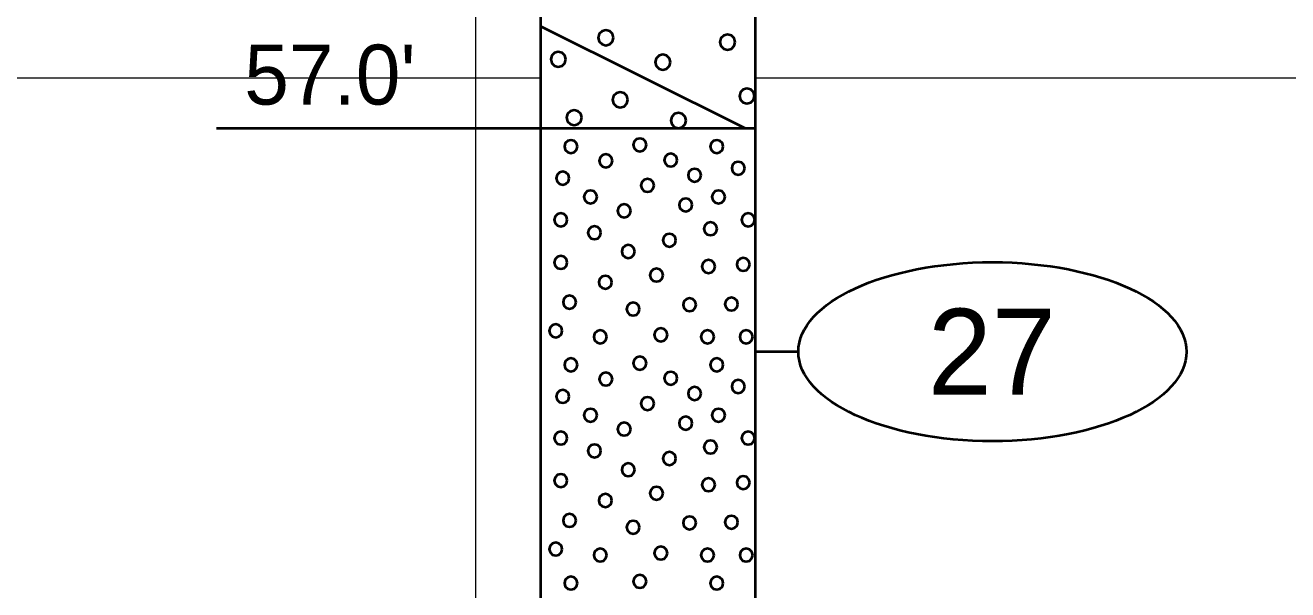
# Model space of a CAD drawing. Extents: x -76 to 974, y -1080 to -735.
# Drawn here: x 658.81 to 673.49, y -988.05 to -981.48 of the extents above; entities that cross this region are included whole.
import ezdxf
from ezdxf.enums import TextEntityAlignment as Align

# ---------------------------------------------------------------- set-up
doc = ezdxf.new("R2010")
doc.units = 0
doc.header["$LTSCALE"] = 0.36
doc.layers.add('27', color=7, linetype='Continuous', lineweight=40)
doc.layers.add('7', color=7, linetype='Continuous', lineweight=13)

msp = doc.modelspace()

# ---------------------------------------------------------------- linework, layer by layer
at = {"layer": '27'}
for p, q in [((664.7963, -977.6789), (664.7963, -982.6789)), ((667.2963, -982.6789), (667.2963, -977.6789)), ((664.7963, -981.4889), (667.1763, -982.6789)), ((661.0289, -982.6789), (664.7963, -982.6789)), ((664.7963, -982.6789), (667.2963, -982.6789)), ((664.7963, -982.6789), (664.7963, -995.7789)), ((667.2963, -995.7789), (667.2963, -982.6789)), ((667.7963, -985.2789), (667.2963, -985.2789))]:
    msp.add_line(p, q, dxfattribs=at)
for points in [[(665.6469, -981.624), (665.635, -981.5796), (665.6025, -981.5471), (665.558, -981.5351), (665.5136, -981.5471), (665.481, -981.5796), (665.4691, -981.624), (665.481, -981.6685), (665.5136, -981.701), (665.558, -981.7129), (665.6025, -981.701), (665.635, -981.6685)], [(667.0618, -981.6749), (667.0499, -981.6304), (667.0174, -981.5979), (666.9729, -981.586), (666.9285, -981.5979), (666.896, -981.6304), (666.884, -981.6749), (666.896, -981.7193), (666.9285, -981.7519), (666.9729, -981.7638), (667.0174, -981.7519), (667.0499, -981.7193)], [(665.0939, -981.8758), (665.082, -981.8313), (665.0495, -981.7988), (665.005, -981.7869), (664.9606, -981.7988), (664.928, -981.8313), (664.9161, -981.8758), (664.928, -981.9202), (664.9606, -981.9527), (665.005, -981.9647), (665.0495, -981.9527), (665.082, -981.9202)], [(666.3093, -981.9088), (666.2973, -981.8644), (666.2648, -981.8318), (666.2204, -981.8199), (666.1759, -981.8318), (666.1434, -981.8644), (666.1315, -981.9088), (666.1434, -981.9533), (666.1759, -981.9858), (666.2204, -981.9977), (666.2648, -981.9858), (666.2973, -981.9533)], [(667.2881, -982.3029), (667.2762, -982.2585), (667.2437, -982.2259), (667.1992, -982.214), (667.1548, -982.2259), (667.1222, -982.2585), (667.1103, -982.3029), (667.1222, -982.3474), (667.1548, -982.3799), (667.1992, -982.3918), (667.2437, -982.3799), (667.2762, -982.3474)], [(665.8135, -982.3461), (665.8015, -982.3017), (665.769, -982.2691), (665.7246, -982.2572), (665.6801, -982.2691), (665.6476, -982.3017), (665.6357, -982.3461), (665.6476, -982.3906), (665.6801, -982.4231), (665.7246, -982.435), (665.769, -982.4231), (665.8015, -982.3906)], [(665.2783, -982.5546), (665.2663, -982.5102), (665.2338, -982.4776), (665.1894, -982.4657), (665.1449, -982.4776), (665.1124, -982.5102), (665.1005, -982.5546), (665.1124, -982.5991), (665.1449, -982.6316), (665.1894, -982.6435), (665.2338, -982.6316), (665.2663, -982.5991)], [(666.491, -982.5877), (666.4791, -982.5432), (666.4466, -982.5107), (666.4021, -982.4988), (666.3577, -982.5107), (666.3252, -982.5432), (666.3132, -982.5877), (666.3252, -982.6321), (666.3577, -982.6647), (666.4021, -982.6766), (666.4466, -982.6647), (666.4791, -982.6321)], [(665.2282, -982.8916), (665.218, -982.8535), (665.1901, -982.8256), (665.152, -982.8154), (665.1139, -982.8256), (665.086, -982.8535), (665.0758, -982.8916), (665.086, -982.9297), (665.1139, -982.9575), (665.152, -982.9678), (665.1901, -982.9575), (665.218, -982.9297)], [(666.0292, -982.872), (666.019, -982.8339), (665.9911, -982.806), (665.953, -982.7958), (665.9149, -982.806), (665.887, -982.8339), (665.8768, -982.872), (665.887, -982.9101), (665.9149, -982.938), (665.953, -982.9482), (665.9911, -982.938), (666.019, -982.9101)], [(666.9228, -982.8916), (666.9126, -982.8535), (666.8847, -982.8256), (666.8466, -982.8154), (666.8085, -982.8256), (666.7807, -982.8535), (666.7704, -982.8916), (666.7807, -982.9297), (666.8085, -982.9576), (666.8466, -982.9678), (666.8847, -982.9576), (666.9126, -982.9297)], [(666.3883, -983.0478), (666.3781, -983.0097), (666.3502, -982.9818), (666.3121, -982.9716), (666.274, -982.9818), (666.2461, -983.0097), (666.2359, -983.0478), (666.2461, -983.0859), (666.274, -983.1138), (666.3121, -983.124), (666.3502, -983.1138), (666.3781, -983.0859)], [(665.6332, -983.0568), (665.623, -983.0187), (665.5951, -982.9908), (665.557, -982.9806), (665.5189, -982.9908), (665.491, -983.0187), (665.4808, -983.0568), (665.491, -983.0949), (665.5189, -983.1228), (665.557, -983.133), (665.5951, -983.1228), (665.623, -983.0949)], [(667.1737, -983.1437), (667.1635, -983.1056), (667.1356, -983.0777), (667.0975, -983.0675), (667.0594, -983.0777), (667.0315, -983.1056), (667.0213, -983.1437), (667.0315, -983.1818), (667.0594, -983.2097), (667.0975, -983.2199), (667.1356, -983.2097), (667.1635, -983.1818)], [(665.1321, -983.2594), (665.1218, -983.2213), (665.094, -983.1934), (665.0559, -983.1832), (665.0178, -983.1934), (664.9899, -983.2213), (664.9797, -983.2594), (664.9899, -983.2975), (665.0178, -983.3254), (665.0559, -983.3356), (665.094, -983.3254), (665.1218, -983.2975)], [(666.1181, -983.3426), (666.1079, -983.3045), (666.08, -983.2766), (666.0419, -983.2664), (666.0038, -983.2766), (665.9759, -983.3045), (665.9657, -983.3426), (665.9759, -983.3807), (666.0038, -983.4086), (666.0419, -983.4188), (666.08, -983.4086), (666.1079, -983.3807)], [(666.6665, -983.2251), (666.6563, -983.187), (666.6284, -983.1591), (666.5903, -983.1489), (666.5522, -983.1591), (666.5243, -983.187), (666.5141, -983.2251), (666.5243, -983.2632), (666.5522, -983.2911), (666.5903, -983.3013), (666.6284, -983.2911), (666.6563, -983.2632)], [(665.455, -983.4781), (665.4447, -983.44), (665.4169, -983.4121), (665.3788, -983.4019), (665.3407, -983.4121), (665.3128, -983.44), (665.3026, -983.4781), (665.3128, -983.5162), (665.3407, -983.5441), (665.3788, -983.5543), (665.4169, -983.5441), (665.4447, -983.5162)], [(666.9436, -983.4781), (666.9334, -983.44), (666.9055, -983.4121), (666.8674, -983.4019), (666.8293, -983.4121), (666.8014, -983.44), (666.7912, -983.4781), (666.8014, -983.5162), (666.8293, -983.5441), (666.8674, -983.5543), (666.9055, -983.5441), (666.9334, -983.5162)], [(665.8465, -983.6395), (665.8363, -983.6014), (665.8084, -983.5735), (665.7703, -983.5633), (665.7322, -983.5735), (665.7043, -983.6014), (665.6941, -983.6395), (665.7043, -983.6776), (665.7322, -983.7055), (665.7703, -983.7157), (665.8084, -983.7055), (665.8363, -983.6776)], [(666.5622, -983.5709), (666.552, -983.5328), (666.5241, -983.5049), (666.486, -983.4947), (666.4479, -983.5049), (666.42, -983.5328), (666.4098, -983.5709), (666.42, -983.609), (666.4479, -983.6369), (666.486, -983.6471), (666.5241, -983.6369), (666.552, -983.609)], [(665.1092, -983.7438), (665.099, -983.7057), (665.0711, -983.6778), (665.033, -983.6676), (664.9949, -983.6778), (664.967, -983.7057), (664.9568, -983.7438), (664.967, -983.7819), (664.9949, -983.8097), (665.033, -983.82), (665.0711, -983.8097), (665.099, -983.7819)], [(667.2894, -983.7438), (667.2792, -983.7057), (667.2513, -983.6778), (667.2132, -983.6676), (667.1751, -983.6778), (667.1472, -983.7057), (667.137, -983.7438), (667.1472, -983.7819), (667.1751, -983.8097), (667.2132, -983.82), (667.2513, -983.8097), (667.2792, -983.7819)], [(665.5007, -983.8938), (665.4905, -983.8557), (665.4626, -983.8278), (665.4245, -983.8176), (665.3864, -983.8278), (665.3585, -983.8557), (665.3483, -983.8938), (665.3585, -983.9319), (665.3864, -983.9598), (665.4245, -983.97), (665.4626, -983.9598), (665.4905, -983.9319)], [(666.8508, -983.848), (666.8406, -983.8099), (666.8127, -983.782), (666.7746, -983.7718), (666.7365, -983.782), (666.7086, -983.8099), (666.6984, -983.848), (666.7086, -983.8861), (666.7365, -983.914), (666.7746, -983.9242), (666.8127, -983.914), (666.8406, -983.8861)], [(666.3728, -983.9815), (666.3626, -983.9434), (666.3347, -983.9155), (666.2966, -983.9053), (666.2585, -983.9155), (666.2306, -983.9434), (666.2204, -983.9815), (666.2306, -984.0196), (666.2585, -984.0475), (666.2966, -984.0577), (666.3347, -984.0475), (666.3626, -984.0196)], [(665.8948, -984.1124), (665.8846, -984.0743), (665.8567, -984.0464), (665.8186, -984.0362), (665.7805, -984.0464), (665.7526, -984.0743), (665.7424, -984.1124), (665.7526, -984.1505), (665.7805, -984.1784), (665.8186, -984.1886), (665.8567, -984.1784), (665.8846, -984.1505)], [(665.1092, -984.2396), (665.099, -984.2015), (665.0711, -984.1736), (665.033, -984.1634), (664.9949, -984.1736), (664.967, -984.2015), (664.9568, -984.2396), (664.967, -984.2777), (664.9949, -984.3055), (665.033, -984.3158), (665.0711, -984.3055), (665.099, -984.2777)], [(666.8279, -984.2866), (666.8177, -984.2485), (666.7898, -984.2206), (666.7517, -984.2104), (666.7136, -984.2206), (666.6857, -984.2485), (666.6755, -984.2866), (666.6857, -984.3247), (666.7136, -984.3526), (666.7517, -984.3628), (666.7898, -984.3526), (666.8177, -984.3247)], [(667.2322, -984.2624), (667.222, -984.2243), (667.1941, -984.1964), (667.156, -984.1862), (667.1179, -984.1964), (667.09, -984.2243), (667.0798, -984.2624), (667.09, -984.3005), (667.1179, -984.3284), (667.156, -984.3386), (667.1941, -984.3284), (667.222, -984.3005)], [(665.6279, -984.4709), (665.6176, -984.4328), (665.5898, -984.4049), (665.5517, -984.3947), (665.5136, -984.4049), (665.4857, -984.4328), (665.4755, -984.4709), (665.4857, -984.509), (665.5136, -984.5369), (665.5517, -984.5471), (665.5898, -984.5369), (665.6176, -984.509)], [(666.2228, -984.387), (666.2126, -984.3489), (666.1847, -984.321), (666.1466, -984.3108), (666.1085, -984.321), (666.0806, -984.3489), (666.0704, -984.387), (666.0806, -984.4251), (666.1085, -984.453), (666.1466, -984.4632), (666.1847, -984.453), (666.2126, -984.4251)], [(665.2121, -984.7023), (665.2019, -984.6642), (665.174, -984.6363), (665.1359, -984.6261), (665.0978, -984.6363), (665.07, -984.6642), (665.0597, -984.7023), (665.07, -984.7404), (665.0978, -984.7683), (665.1359, -984.7785), (665.174, -984.7683), (665.2019, -984.7404)], [(665.9508, -984.7824), (665.9405, -984.7443), (665.9127, -984.7164), (665.8746, -984.7062), (665.8365, -984.7164), (665.8086, -984.7443), (665.7984, -984.7824), (665.8086, -984.8205), (665.8365, -984.8484), (665.8746, -984.8586), (665.9127, -984.8484), (665.9405, -984.8205)], [(666.608, -984.7315), (666.5978, -984.6934), (666.5699, -984.6655), (666.5318, -984.6553), (666.4937, -984.6655), (666.4658, -984.6934), (666.4556, -984.7315), (666.4658, -984.7696), (666.4937, -984.7975), (666.5318, -984.8077), (666.5699, -984.7975), (666.5978, -984.7696)], [(667.0936, -984.7239), (667.0834, -984.6858), (667.0555, -984.6579), (667.0174, -984.6477), (666.9793, -984.6579), (666.9514, -984.6858), (666.9412, -984.7239), (666.9514, -984.762), (666.9793, -984.7899), (667.0174, -984.8001), (667.0555, -984.7899), (667.0834, -984.762)], [(665.0507, -985.0354), (665.0405, -984.9973), (665.0126, -984.9694), (664.9745, -984.9592), (664.9364, -984.9694), (664.9085, -984.9973), (664.8983, -985.0354), (664.9085, -985.0735), (664.9364, -985.1014), (664.9745, -985.1116), (665.0126, -985.1014), (665.0405, -985.0735)], [(665.5694, -985.1053), (665.5592, -985.0672), (665.5313, -985.0393), (665.4932, -985.0291), (665.4551, -985.0393), (665.4272, -985.0672), (665.417, -985.1053), (665.4272, -985.1434), (665.4551, -985.1713), (665.4932, -985.1815), (665.5313, -985.1713), (665.5592, -985.1434)], [(666.2737, -985.0824), (666.2634, -985.0443), (666.2356, -985.0164), (666.1975, -985.0062), (666.1594, -985.0164), (666.1315, -985.0443), (666.1213, -985.0824), (666.1315, -985.1205), (666.1594, -985.1484), (666.1975, -985.1586), (666.2356, -985.1484), (666.2634, -985.1205)], [(666.8165, -985.1053), (666.8063, -985.0672), (666.7784, -985.0393), (666.7403, -985.0291), (666.7022, -985.0393), (666.6743, -985.0672), (666.6641, -985.1053), (666.6743, -985.1434), (666.7022, -985.1713), (666.7403, -985.1815), (666.7784, -985.1713), (666.8063, -985.1434)], [(667.2665, -985.1053), (667.2563, -985.0672), (667.2284, -985.0393), (667.1903, -985.0291), (667.1522, -985.0393), (667.1243, -985.0672), (667.1141, -985.1053), (667.1243, -985.1434), (667.1522, -985.1713), (667.1903, -985.1815), (667.2284, -985.1713), (667.2563, -985.1434)], [(665.2282, -985.4316), (665.218, -985.3935), (665.1901, -985.3656), (665.152, -985.3554), (665.1139, -985.3656), (665.086, -985.3935), (665.0758, -985.4316), (665.086, -985.4697), (665.1139, -985.4975), (665.152, -985.5078), (665.1901, -985.4975), (665.218, -985.4697)], [(666.0292, -985.412), (666.019, -985.3739), (665.9911, -985.346), (665.953, -985.3358), (665.9149, -985.346), (665.887, -985.3739), (665.8768, -985.412), (665.887, -985.4501), (665.9149, -985.478), (665.953, -985.4882), (665.9911, -985.478), (666.019, -985.4501)], [(666.9228, -985.4316), (666.9126, -985.3935), (666.8847, -985.3656), (666.8466, -985.3554), (666.8085, -985.3656), (666.7807, -985.3935), (666.7704, -985.4316), (666.7807, -985.4697), (666.8085, -985.4976), (666.8466, -985.5078), (666.8847, -985.4976), (666.9126, -985.4697)], [(665.6332, -985.5968), (665.623, -985.5587), (665.5951, -985.5308), (665.557, -985.5206), (665.5189, -985.5308), (665.491, -985.5587), (665.4808, -985.5968), (665.491, -985.6349), (665.5189, -985.6628), (665.557, -985.673), (665.5951, -985.6628), (665.623, -985.6349)], [(666.3883, -985.5878), (666.3781, -985.5497), (666.3502, -985.5218), (666.3121, -985.5116), (666.274, -985.5218), (666.2461, -985.5497), (666.2359, -985.5878), (666.2461, -985.6259), (666.274, -985.6538), (666.3121, -985.664), (666.3502, -985.6538), (666.3781, -985.6259)], [(667.1737, -985.6837), (667.1635, -985.6456), (667.1356, -985.6177), (667.0975, -985.6075), (667.0594, -985.6177), (667.0315, -985.6456), (667.0213, -985.6837), (667.0315, -985.7218), (667.0594, -985.7497), (667.0975, -985.7599), (667.1356, -985.7497), (667.1635, -985.7218)], [(665.1321, -985.7994), (665.1218, -985.7613), (665.094, -985.7334), (665.0559, -985.7232), (665.0178, -985.7334), (664.9899, -985.7613), (664.9797, -985.7994), (664.9899, -985.8375), (665.0178, -985.8654), (665.0559, -985.8756), (665.094, -985.8654), (665.1218, -985.8375)], [(666.6665, -985.7651), (666.6563, -985.727), (666.6284, -985.6991), (666.5903, -985.6889), (666.5522, -985.6991), (666.5243, -985.727), (666.5141, -985.7651), (666.5243, -985.8032), (666.5522, -985.8311), (666.5903, -985.8413), (666.6284, -985.8311), (666.6563, -985.8032)], [(666.1181, -985.8826), (666.1079, -985.8445), (666.08, -985.8166), (666.0419, -985.8064), (666.0038, -985.8166), (665.9759, -985.8445), (665.9657, -985.8826), (665.9759, -985.9207), (666.0038, -985.9486), (666.0419, -985.9588), (666.08, -985.9486), (666.1079, -985.9207)], [(665.455, -986.0181), (665.4447, -985.98), (665.4169, -985.9521), (665.3788, -985.9419), (665.3407, -985.9521), (665.3128, -985.98), (665.3026, -986.0181), (665.3128, -986.0562), (665.3407, -986.0841), (665.3788, -986.0943), (665.4169, -986.0841), (665.4447, -986.0562)], [(666.5622, -986.1109), (666.552, -986.0728), (666.5241, -986.0449), (666.486, -986.0347), (666.4479, -986.0449), (666.42, -986.0728), (666.4098, -986.1109), (666.42, -986.149), (666.4479, -986.1769), (666.486, -986.1871), (666.5241, -986.1769), (666.552, -986.149)], [(666.9436, -986.0181), (666.9334, -985.98), (666.9055, -985.9521), (666.8674, -985.9419), (666.8293, -985.9521), (666.8014, -985.98), (666.7912, -986.0181), (666.8014, -986.0562), (666.8293, -986.0841), (666.8674, -986.0943), (666.9055, -986.0841), (666.9334, -986.0562)], [(665.8465, -986.1795), (665.8363, -986.1414), (665.8084, -986.1135), (665.7703, -986.1033), (665.7322, -986.1135), (665.7043, -986.1414), (665.6941, -986.1795), (665.7043, -986.2176), (665.7322, -986.2455), (665.7703, -986.2557), (665.8084, -986.2455), (665.8363, -986.2176)], [(665.1092, -986.2838), (665.099, -986.2457), (665.0711, -986.2178), (665.033, -986.2076), (664.9949, -986.2178), (664.967, -986.2457), (664.9568, -986.2838), (664.967, -986.3219), (664.9949, -986.3497), (665.033, -986.36), (665.0711, -986.3497), (665.099, -986.3219)], [(666.8508, -986.388), (666.8406, -986.3499), (666.8127, -986.322), (666.7746, -986.3118), (666.7365, -986.322), (666.7086, -986.3499), (666.6984, -986.388), (666.7086, -986.4261), (666.7365, -986.454), (666.7746, -986.4642), (666.8127, -986.454), (666.8406, -986.4261)], [(667.2894, -986.2838), (667.2792, -986.2457), (667.2513, -986.2178), (667.2132, -986.2076), (667.1751, -986.2178), (667.1472, -986.2457), (667.137, -986.2838), (667.1472, -986.3219), (667.1751, -986.3497), (667.2132, -986.36), (667.2513, -986.3497), (667.2792, -986.3219)], [(665.5007, -986.4338), (665.4905, -986.3957), (665.4626, -986.3678), (665.4245, -986.3576), (665.3864, -986.3678), (665.3585, -986.3957), (665.3483, -986.4338), (665.3585, -986.4719), (665.3864, -986.4998), (665.4245, -986.51), (665.4626, -986.4998), (665.4905, -986.4719)], [(666.3728, -986.5215), (666.3626, -986.4834), (666.3347, -986.4555), (666.2966, -986.4453), (666.2585, -986.4555), (666.2306, -986.4834), (666.2204, -986.5215), (666.2306, -986.5596), (666.2585, -986.5875), (666.2966, -986.5977), (666.3347, -986.5875), (666.3626, -986.5596)], [(665.8948, -986.6524), (665.8846, -986.6143), (665.8567, -986.5864), (665.8186, -986.5762), (665.7805, -986.5864), (665.7526, -986.6143), (665.7424, -986.6524), (665.7526, -986.6905), (665.7805, -986.7184), (665.8186, -986.7286), (665.8567, -986.7184), (665.8846, -986.6905)], [(665.1092, -986.7796), (665.099, -986.7415), (665.0711, -986.7136), (665.033, -986.7034), (664.9949, -986.7136), (664.967, -986.7415), (664.9568, -986.7796), (664.967, -986.8177), (664.9949, -986.8455), (665.033, -986.8558), (665.0711, -986.8455), (665.099, -986.8177)], [(666.8279, -986.8266), (666.8177, -986.7885), (666.7898, -986.7606), (666.7517, -986.7504), (666.7136, -986.7606), (666.6857, -986.7885), (666.6755, -986.8266), (666.6857, -986.8647), (666.7136, -986.8926), (666.7517, -986.9028), (666.7898, -986.8926), (666.8177, -986.8647)], [(667.2322, -986.8024), (667.222, -986.7643), (667.1941, -986.7364), (667.156, -986.7262), (667.1179, -986.7364), (667.09, -986.7643), (667.0798, -986.8024), (667.09, -986.8405), (667.1179, -986.8684), (667.156, -986.8786), (667.1941, -986.8684), (667.222, -986.8405)], [(665.6279, -987.0109), (665.6176, -986.9728), (665.5898, -986.9449), (665.5517, -986.9347), (665.5136, -986.9449), (665.4857, -986.9728), (665.4755, -987.0109), (665.4857, -987.049), (665.5136, -987.0769), (665.5517, -987.0871), (665.5898, -987.0769), (665.6176, -987.049)], [(666.2228, -986.927), (666.2126, -986.8889), (666.1847, -986.861), (666.1466, -986.8508), (666.1085, -986.861), (666.0806, -986.8889), (666.0704, -986.927), (666.0806, -986.9651), (666.1085, -986.993), (666.1466, -987.0032), (666.1847, -986.993), (666.2126, -986.9651)], [(665.2121, -987.2423), (665.2019, -987.2042), (665.174, -987.1763), (665.1359, -987.1661), (665.0978, -987.1763), (665.07, -987.2042), (665.0597, -987.2423), (665.07, -987.2804), (665.0978, -987.3083), (665.1359, -987.3185), (665.174, -987.3083), (665.2019, -987.2804)], [(666.608, -987.2715), (666.5978, -987.2334), (666.5699, -987.2055), (666.5318, -987.1953), (666.4937, -987.2055), (666.4658, -987.2334), (666.4556, -987.2715), (666.4658, -987.3096), (666.4937, -987.3375), (666.5318, -987.3477), (666.5699, -987.3375), (666.5978, -987.3096)], [(667.0936, -987.2639), (667.0834, -987.2258), (667.0555, -987.1979), (667.0174, -987.1877), (666.9793, -987.1979), (666.9514, -987.2258), (666.9412, -987.2639), (666.9514, -987.302), (666.9793, -987.3299), (667.0174, -987.3401), (667.0555, -987.3299), (667.0834, -987.302)], [(665.9508, -987.3224), (665.9405, -987.2843), (665.9127, -987.2564), (665.8746, -987.2462), (665.8365, -987.2564), (665.8086, -987.2843), (665.7984, -987.3224), (665.8086, -987.3605), (665.8365, -987.3884), (665.8746, -987.3986), (665.9127, -987.3884), (665.9405, -987.3605)], [(665.0507, -987.5754), (665.0405, -987.5373), (665.0126, -987.5094), (664.9745, -987.4992), (664.9364, -987.5094), (664.9085, -987.5373), (664.8983, -987.5754), (664.9085, -987.6135), (664.9364, -987.6414), (664.9745, -987.6516), (665.0126, -987.6414), (665.0405, -987.6135)], [(665.5694, -987.6453), (665.5592, -987.6072), (665.5313, -987.5793), (665.4932, -987.5691), (665.4551, -987.5793), (665.4272, -987.6072), (665.417, -987.6453), (665.4272, -987.6834), (665.4551, -987.7113), (665.4932, -987.7215), (665.5313, -987.7113), (665.5592, -987.6834)], [(666.2737, -987.6224), (666.2634, -987.5843), (666.2356, -987.5564), (666.1975, -987.5462), (666.1594, -987.5564), (666.1315, -987.5843), (666.1213, -987.6224), (666.1315, -987.6605), (666.1594, -987.6884), (666.1975, -987.6986), (666.2356, -987.6884), (666.2634, -987.6605)], [(666.8165, -987.6453), (666.8063, -987.6072), (666.7784, -987.5793), (666.7403, -987.5691), (666.7022, -987.5793), (666.6743, -987.6072), (666.6641, -987.6453), (666.6743, -987.6834), (666.7022, -987.7113), (666.7403, -987.7215), (666.7784, -987.7113), (666.8063, -987.6834)], [(667.2665, -987.6453), (667.2563, -987.6072), (667.2284, -987.5793), (667.1903, -987.5691), (667.1522, -987.5793), (667.1243, -987.6072), (667.1141, -987.6453), (667.1243, -987.6834), (667.1522, -987.7113), (667.1903, -987.7215), (667.2284, -987.7113), (667.2563, -987.6834)], [(665.2282, -987.9716), (665.218, -987.9335), (665.1901, -987.9056), (665.152, -987.8954), (665.1139, -987.9056), (665.086, -987.9335), (665.0758, -987.9716), (665.086, -988.0097), (665.1139, -988.0375), (665.152, -988.0478), (665.1901, -988.0375), (665.218, -988.0097)], [(666.0292, -987.952), (666.019, -987.9139), (665.9911, -987.886), (665.953, -987.8758), (665.9149, -987.886), (665.887, -987.9139), (665.8768, -987.952), (665.887, -987.9901), (665.9149, -988.018), (665.953, -988.0282), (665.9911, -988.018), (666.019, -987.9901)], [(666.9228, -987.9716), (666.9126, -987.9335), (666.8847, -987.9056), (666.8466, -987.8954), (666.8085, -987.9056), (666.7807, -987.9335), (666.7704, -987.9716), (666.7807, -988.0097), (666.8085, -988.0376), (666.8466, -988.0478), (666.8847, -988.0376), (666.9126, -988.0097)]]:
    msp.add_lwpolyline(points, close=True, dxfattribs=at)
msp.add_ellipse((670.0537, -985.2789), major_axis=(2.2574, 0), ratio=0.461538, dxfattribs=at)
at = {"layer": '7'}
for p, q in [((664.0463, -1042.0988), (664.0463, -895.7205)), ((609.6738, -982.09), (664.7963, -982.09)), ((667.2963, -982.09), (678.7313, -982.09))]:
    msp.add_line(p, q, dxfattribs=at)

# ---------------------------------------------------------------- texts
at = {"layer": '27'}
msp.add_text("57.0'", height=0.6976, dxfattribs=at).set_placement((661.3529, -982.4025))
msp.add_text('27', height=1, dxfattribs=at).set_placement((670.0465, -985.7788), align=Align.CENTER)

doc.saveas('drawing.dxf')
